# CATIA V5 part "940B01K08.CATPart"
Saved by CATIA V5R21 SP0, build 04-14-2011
Part number: 940B01K08
Bounding box of the stored display mesh (mm): x -8.5 to 164.5, y -7 to 7, z -25.901 to 9.099
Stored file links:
  C:\Users\ALI OZGUN\Desktop\alhan\940B01K08.CATPart
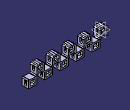
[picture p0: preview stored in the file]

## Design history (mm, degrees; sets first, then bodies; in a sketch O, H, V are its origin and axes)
Body1 (main body)
  Sketch1 on zx-plane, origin (0, 0, 0), H (-1, 0, 0), V (0, 0, 1)
    point P1 (-8.5, -8.9006)
    line L1 (-8.5, -7.9006) -> (-8, -7.4006)
    point P2 (-8, -7.4006)
    line L2 (-8, -7.4006) -> (-8, 6.6246)
    point P3 (-8, 6.6246)
    line L3 (-8, 6.6246) -> (-5.5251, 9.0994)
    point P4 (-5.5251, 9.0994)
    line L4 (-5.5251, 9.0994) -> (0, 9.0994)
    point P5 (0, 9.0994)
    line L5 (-8.5, -7.9006) -> (-8.5, -11.9006)
    point P6 (-8.5, -11.9006)
    line L6 (-8.5, -11.9006) -> (-5, -8.4006)
    point P7 (-3.5, -6.9006)
    line L7 (-5, -6.9006) -> (0, -6.9006)
    point P8 (0, -6.9006)
    line L8 (0, 6.2994) -> (-4.0825, 6.2994)
    point P9 (-4.0825, 6.2994)
    line L9 (-4.0825, 6.2994) -> (-5.2, 5.1819)
    point P10 (-5.2, 5.1819)
    line L10 (-5.2, 5.1819) -> (-5.2, -3.4006)
    point P11 (-5.2, -3.4006)
    line L11 (-5.2, -3.4006) -> (0, -3.4006)
    point P12 (0, -3.4006)
    point P13 (-8.5, -7.9006)
    point P14 (8, -7.4006)
    point P15 (8.5, -7.9006)
    line L12 (8.5, -7.9006) -> (8, -7.4006)
    point P16 (8, 6.6246)
    line L13 (8, -7.4006) -> (8, 6.6246)
    point P17 (5.5251, 9.0994)
    line L14 (8, 6.6246) -> (5.5251, 9.0994)
    point P18 (8.5, -11.9006)
    line L15 (8.5, -7.9006) -> (8.5, -11.9006)
    point P19 (3.5, -6.9006)
    line L16 (8.5, -11.9006) -> (5, -8.4006)
    point P20 (5.2, 5.1819)
    point P21 (4.0825, 6.2994)
    line L17 (4.0825, 6.2994) -> (5.2, 5.1819)
    point P22 (5.2, -3.4006)
    line L18 (5.2, 5.1819) -> (5.2, -3.4006)
    point P23 (0, -6.9006)
    line L19 (5, -6.9006) -> (0, -6.9006)
    point P24 (0, -3.4006)
    line L20 (5.2, -3.4006) -> (0, -3.4006)
    line L21 (0, 6.2994) -> (4.0825, 6.2994)
    point P25 (0, 9.0994)
    line L22 (5.5251, 9.0994) -> (0, 9.0994)
    point P26 (0, 6.2994)
    point P27 (0, 6.2994)
    line L23 (-5, -6.9006) -> (-5, -8.4006)
    line L24 (5, -6.9006) -> (5, -8.4006)
    distance L2 V = 8
    angle L3 L2 = 135
    distance L4 H = 9.0994
    distance L8 L4 = 2.8
    distance L10 L2 = 2.8
    distance L11 L7 = 3.5
    distance L9 L3 = 3
    length L3 = 3.5
    distance L4 L7 = 16
    distance L4 P6 = 21
    distance L5 L2 = 0.5
    length L5 = 4
    distance L23 L2 = 3
    vertical: L2 V, L5 V, L10 V, L23 V
    parallelism: L3 L1, L6 L1
    horizontal: L4 H, L7 H, L8 H, L11 H
    coincidence: P5 V, P8 V, P12 V, P1 L5, P26 V, P27 V, P5 P25, P8 P23, P12 P24, P26 P27, P7 L7, P7 L6, P19 L16, P19 L19
    symmetry: P2 P14 V, P13 P15 V, L1 L12 V, P3 P16 V, L2 L13 V, P4 P17 V, L3 L14 V, P6 P18 V, L5 L15 V, P7 P19 V, L6 L16 V, P10 P20 V, P9 P21 V, L9 L17 V, P11 P22 V, L10 L18 V, P8 P23 V, L7 L19 V, P12 P24 V, L11 L20 V, L8 L21 V, P5 P25 V, L4 L22 V, L23 L24 V
  Pad1: profile Sketch1, direction (0, 1, 0), length 7, mirrored extent
  Fillet1: radius 3, on edge [face of Pad1 from Sketch1.L22 | face of Pad1 from Sketch1.L14]; edge [face of Pad1 from Sketch1.L3 | face of Pad1 from Sketch1.L4]; edge [face of Pad1 from Sketch1.L2 | face of Pad1 from Sketch1.L3]; edge [face of Pad1 from Sketch1.L14 | face of Pad1 from Sketch1.L13]
  Fillet2: radius 1, on edge [face of Pad1 from Sketch1.L17 | face of Pad1 from Sketch1.L21]; edge [face of Pad1 from Sketch1.L18 | face of Pad1 from Sketch1.L17]; edge [face of Pad1 from Sketch1.L8 | face of Pad1 from Sketch1.L9]; edge [face of Pad1 from Sketch1.L9 | face of Pad1 from Sketch1.L10]
  Fillet3: radius 2, on edge [face of Pad1 from Sketch1.L23 | face of Pad1 from Sketch1.L6]; edge [face of Pad1 from Sketch1.L16 | face of Pad1 from Sketch1.L24]
  Fillet4: radius 1.5, on edge [face of Pad1 from Sketch1.L20 | face of Pad1 from Sketch1.L18]; edge [face of Pad1 from Sketch1.L10 | face of Pad1 from Sketch1.L11]
  Body2
    Sketch2 on zx-plane, origin (0, 0, 0), H (-1, 0, 0), V (0, 0, 1)
      line L1 (-8.5, -7.9006) -> (-10.5, -9.9006)
      line L2 (-10.5, -9.9006) -> (-17.3, -9.9006)
      line L3 (-8.5, -11.9006) -> (-9.05, -12.4506)
      line L4 (-9.05, -12.4506) -> (-9.05, -25.9006)
      line L5 (-9.05, -25.9006) -> (-17.3, -25.9006)
      line L6 (-17.3, -22.7006) -> (-11.85, -22.7006)
      line L7 (-11.85, -22.7006) -> (-11.85, -13.1006)
      line L8 (-11.85, -13.1006) -> (-17.3, -13.1006)
      axis line L9 (-17.3, -4.8689) -> (-17.3, -27.5881)
      point P6 (-17.3, -9.9006)
      point P7 (-17.3, -13.1006)
      point P8 (-17.3, -22.7006)
      point P9 (-17.3, -25.9006)
      reference projected line E1 (0, 9.0994) -> (-5.5251, 9.0994) from edge [face of Pad1 from Sketch1.L4 | end face of Pad1]
      reference projected line E2 (-8.5, -11.9006) -> (-5, -8.4006) from edge [face of Pad1 from Sketch1.L6 | end face of Pad1]
      reference projected line E3 (-8, -7.4006) -> (-8.5, -7.9006) from edge [face of Pad1 from Sketch1.L1 | end face of Pad1]
      projected line E4 (-8.5, -7.9006) -> (-8.5, -11.9006) from edge [face of Pad1 from Sketch1.L5 | end face of Pad1]
      projected line E5 (-8.5, -7.9006) -> (-8.5, -11.9006) from edge [face of Pad1 from Sketch1.L5 | end face of Pad1]
      reference projected line E6 (-8, 6.6246) -> (-8, -7.4006) from edge [face of Pad1 from Sketch1.L2 | end face of Pad1]
      line L10 (-17.3, -9.9006) -> (-17.3, -13.1006)
      line L11 (-17.3, -22.7006) -> (-17.3, -25.9006)
      distance L5 E1 = 35
      distance L2 L5 = 16
      distance L8 L2 = 3.2
      distance L6 L5 = 3.2
      distance L7 L4 = 2.8
      distance L4 E6 = 1.05
      distance L4 L9 = 8.25
      horizontal: L2 H, L5 H, L6 H, L8 H
      vertical: L4 V, L7 V, L9 V, L10 V, L11 V
      coincidence: P6 L9, P7 L9, P8 L9, P9 L9, L3 E2, L1 E3
    Pad2: profile Sketch2, direction (0, 1, 0), length 7, mirrored extent
    Mirror1: of the body so far, about face of Pad2 from Sketch2.L10
    Fillet5: radius 1.5, on edge [face of Pad2 | face of Mirror1] (x2); edge [face of Pad2 from Sketch2.L4 | face of Pad2]; edge [face of Mirror1 | face of Pad2] (x2); edge [face of Pad2 | face of Pad2 from Sketch2.L1]; edge [face of Pad2 from Sketch2.L7 | face of Pad2]; edge [face of Pad2 | face of Pad2 from Sketch2.L7]
  Add1: tool Body2
  RemoveFace1: RemoveFaces (face of Fillet5; face of Fillet1; face of Fillet5; face of Fillet1)
  Thickness1: Face (face of Pad2 from Sketch2.L4; face of Mirror1; face of Pad1 from Sketch1.L2; face of Pad1 from Sketch1.L13), Thickness 0.5
  RectPattern1: of the body so far, direction 1 instances 5, spacing 34.6, along edge [face of Pad1 | face of Pad2]
  Sketch3 on yz-plane, origin (0, 0, 0), H (0, 1, 0), V (0, 0, 1)
    construction line L1 (0, 4.5994) -> (0, -1.4006)
    point P1 (0, 4.5994)
    line L2 (2.5, 4.5994) -> (2.5, -1.4006)
    line L3 (-2.5, -1.4006) -> (-2.5, 4.5994)
    arc A1 centre (0, -1.4006) radius 2.5 from (2.5, -1.4006) to (-2.5, -1.4006) cw
    arc A2 centre (0, 4.5994) radius 2.5 from (-2.5, 4.5994) to (2.5, 4.5994) cw
    construction line L4 (0, -14.8006) -> (0, -20.8006)
    point P7 (0, -14.8006)
    point P8 (0, -20.8006)
    line L5 (2.5, -14.8006) -> (2.5, -20.8006)
    line L6 (-2.5, -20.8006) -> (-2.5, -14.8006)
    arc A3 centre (0, -20.8006) radius 2.5 from (2.5, -20.8006) to (-2.5, -20.8006) cw
    arc A4 centre (0, -14.8006) radius 2.5 from (-2.5, -14.8006) to (2.5, -14.8006) cw
    reference projected line E1 (-7, 9.0994) -> (7, 9.0994) from edge [face of Pad1 from Sketch1.L22 | face of Fillet1]
    distance L1 L2 = 2.5
    distance L4 L5 = 2.5
    length L1 = 6
    length L4 = 6
    distance A2 E1 = 2
    distance P8 P1 = 25.4
    coincidence: P1 V, P7 V
    vertical: L1 V, L4 V
    tangency: A1 L2, A2 L2, A1 L3, A2 L3, A3 L5, A4 L5, A3 L6, A4 L6
  Pocket1: profile Sketch3, direction (-1, 0, 0), through (limit type 3), opposite side through (limit type 3)
Body3
  Solid1: linked copy from another document
  Translate1: Direction xy-plane, ToTransfor Solid1, Length 19.4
